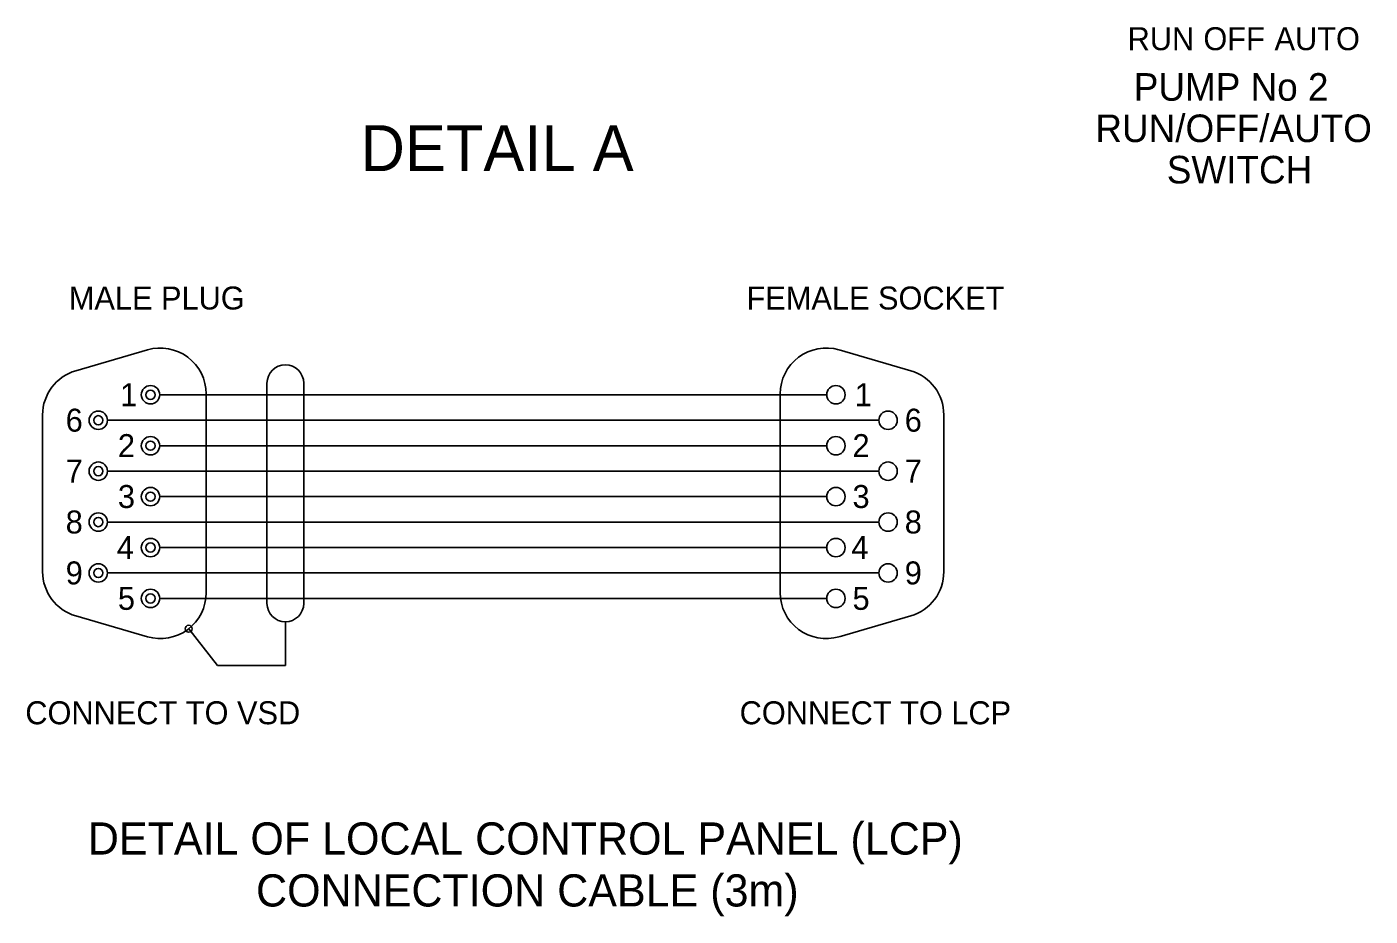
# Model space of a CAD drawing. Extents: x 0 to 841, y 0 to 594.
# Drawn here: x 399.3 to 545.4, y 125.8 to 222.5 of the extents above; entities that cross this region are included whole.
import ezdxf

# ---------------------------------------------------------------- set-up
doc = ezdxf.new("R2010")
doc.units = 0
doc.layers.add('BASE', color=7, linetype='Continuous')
doc.layers.add('Level 1', color=7, linetype='Continuous')

msp = doc.modelspace()

# ---------------------------------------------------------------- linework, layer by layer
at = {"layer": 'BASE'}
for p, q in [((412.38, 187.39), (404.58, 185.12)), ((487.62, 187.39), (495.42, 185.12)), ((425.39, 183.76), (425.39, 159.8)), ((429.39, 183.76), (429.39, 159.8)), ((486.28, 182.5), (413.72, 182.5)), ((418.78, 182.59), (418.78, 160.97)), ((481.22, 182.59), (481.22, 160.97)), ((400.98, 180.32), (400.98, 163.24)), ((499.02, 180.32), (499.02, 163.24)), ((491.96, 179.73), (408.04, 179.73)), ((486.28, 176.96), (413.72, 176.96)), ((491.96, 174.19), (408.04, 174.19)), ((486.28, 171.42), (413.72, 171.42)), ((491.96, 168.65), (408.04, 168.65)), ((486.28, 165.88), (413.72, 165.88)), ((491.96, 163.11), (408.04, 163.11)), ((486.28, 160.34), (413.72, 160.34)), ((412.38, 156.17), (404.58, 158.44)), ((487.62, 156.17), (495.42, 158.44)), ((416.87, 157.04), (420.02, 153.05)), ((427.39, 157.8), (427.39, 153.05)), ((420.02, 153.05), (427.39, 153.05))]:
    msp.add_line(p, q, dxfattribs=at)
for centre in [(412.72, 182.5), (487.28, 182.5), (407.04, 179.73), (492.96, 179.73), (412.72, 176.96), (487.28, 176.96), (407.04, 174.19), (492.96, 174.19), (412.72, 171.42), (487.28, 171.42), (407.04, 168.65), (492.96, 168.65), (412.72, 165.88), (487.28, 165.88), (407.04, 163.11), (492.96, 163.11), (412.72, 160.34), (487.28, 160.34)]:
    msp.add_circle(centre, 1, dxfattribs=at)
for centre, radius, start, end in [((413.78, 182.59), 5, 0, 106.2177), ((486.22, 182.59), 5, 73.7823, 180), ((427.39, 183.76), 2, 0, 180), ((405.98, 180.32), 5, 106.2177, 180), ((494.02, 180.32), 5, 0, 73.7823), ((412.72, 182.5), 0.5, 0, 180), ((412.72, 182.5), 0.5, 180, 0), ((407.04, 179.73), 0.5, 0, 180), ((407.04, 179.73), 0.5, 180, 0), ((412.72, 176.96), 0.5, 0, 180), ((412.72, 176.96), 0.5, 180, 0), ((407.04, 174.19), 0.5, 0, 180), ((407.04, 174.19), 0.5, 180, 0), ((412.72, 171.42), 0.5, 0, 180), ((412.72, 171.42), 0.5, 180, 0), ((407.04, 168.65), 0.5, 0, 180), ((407.04, 168.65), 0.5, 180, 0), ((412.72, 165.88), 0.5, 0, 180), ((412.72, 165.88), 0.5, 180, 0), ((405.98, 163.24), 5, 180, 253.7823), ((407.04, 163.11), 0.5, 0, 180), ((407.04, 163.11), 0.5, 180, 0), ((494.02, 163.24), 5, 286.2177, 0), ((412.72, 160.34), 0.5, 0, 180), ((413.78, 160.97), 5, 253.7823, 0), ((486.22, 160.97), 5, 180, 286.2177), ((412.72, 160.34), 0.5, 180, 0), ((427.39, 159.8), 2, 180, 0), ((416.87, 157.04), 0.375, 0, 180), ((416.87, 157.04), 0.375, 180, 0)]:
    msp.add_arc(centre, radius, start, end, dxfattribs=at)

# ---------------------------------------------------------------- texts
for s, height, p in [('DETAIL A', 5, (435.56, 206.84)), ('MALE PLUG', 2.5, (403.83, 191.78)), ('FEMALE SOCKET', 2.5, (477.56, 191.78)), ('1', 2.5, (409.42, 181.26)), ('1', 2.5, (489.34, 181.26)), ('6', 2.5, (403.49, 178.49)), ('6', 2.5, (494.77, 178.49)), ('2', 2.5, (409.17, 175.72)), ('2', 2.5, (489.09, 175.72)), ('7', 2.5, (403.49, 172.95)), ('7', 2.5, (494.77, 172.95)), ('3', 2.5, (409.17, 170.18)), ('3', 2.5, (489.09, 170.18)), ('8', 2.5, (403.49, 167.41)), ('8', 2.5, (494.77, 167.41)), ('4', 2.5, (409.05, 164.64)), ('4', 2.5, (488.96, 164.64)), ('9', 2.5, (403.49, 161.87)), ('9', 2.5, (494.77, 161.87)), ('5', 2.5, (409.17, 159.1)), ('5', 2.5, (489.09, 159.1)), ('CONNECT TO VSD', 2.5, (399.1, 146.65)), ('CONNECT TO LCP', 2.5, (476.81, 146.65)), ('DETAIL OF LOCAL CONTROL PANEL (LCP)', 3.5, (405.9, 132.47)), ('CONNECTION CABLE (3m)', 3.5, (424.2, 126.82))]:
    msp.add_text(s, height=height, dxfattribs=at).set_placement(p)
at = {"layer": 'Level 1'}
for s, height, p in [('RUN', 2.5, (519.02, 220)), ('OFF', 2.5, (527.26, 220)), ('AUTO', 2.5, (535, 220)), ('PUMP No 2', 3, (519.69, 214.5)), ('RUN/OFF/AUTO', 3, (515.51, 210)), ('SWITCH', 3, (523.28, 205.5))]:
    msp.add_text(s, height=height, dxfattribs=at).set_placement(p)

doc.saveas('drawing.dxf')
